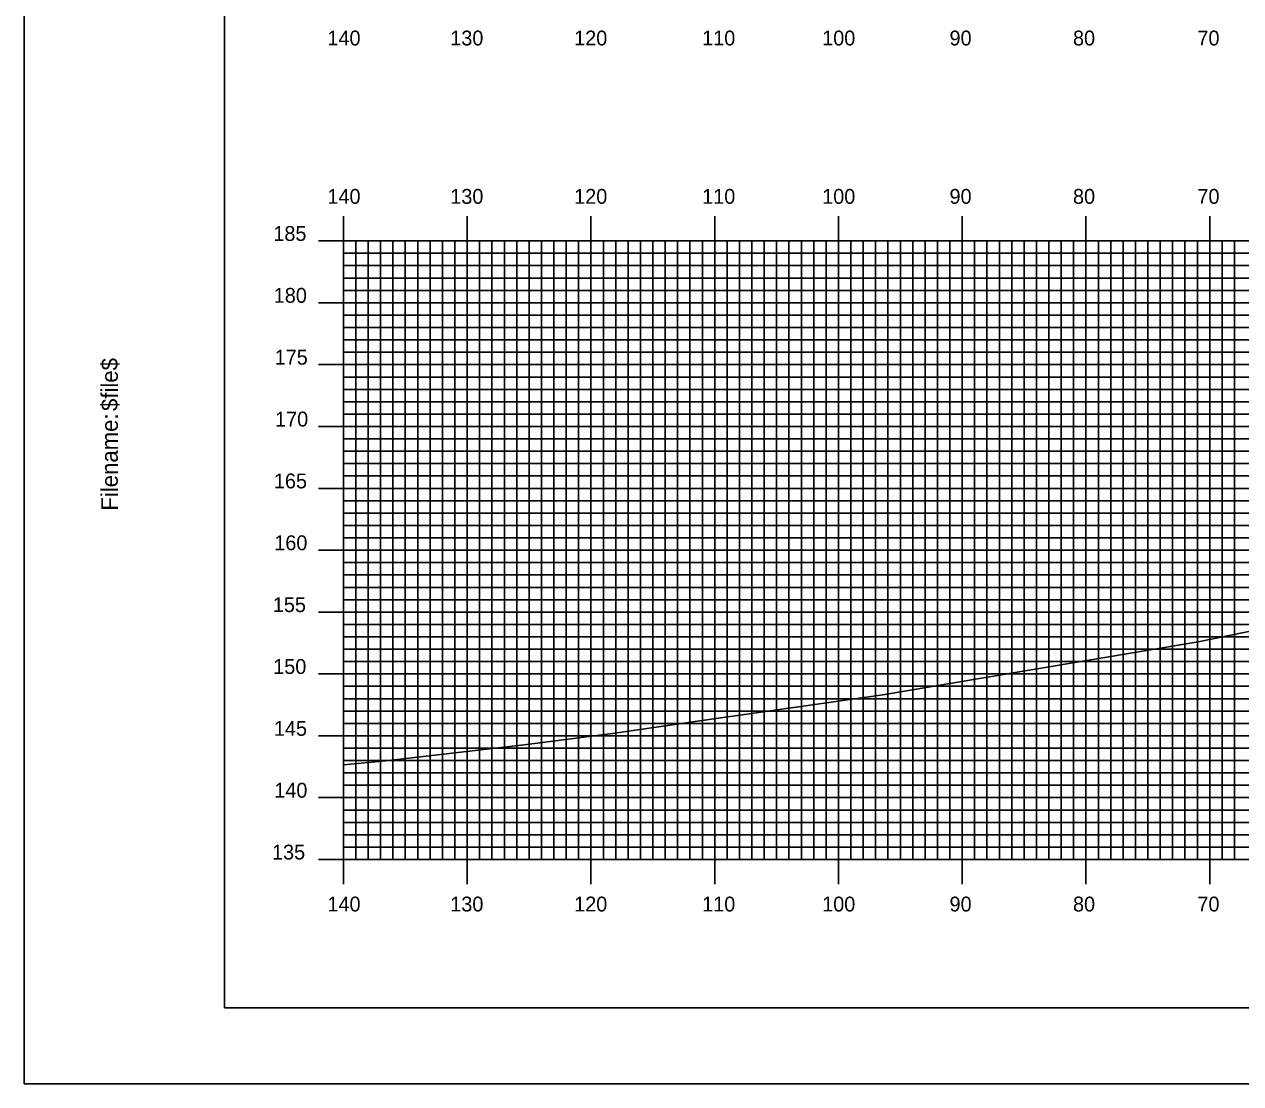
# Model space of a CAD drawing. Extents: x 1793666 to 1794009, y 442591 to 442811.
# Drawn here: x 1793665.5 to 1793763.8, y 442590.5 to 442676.2 of the extents above; entities that cross this region are included whole.
import ezdxf

# ---------------------------------------------------------------- set-up
doc = ezdxf.new("R2010")
doc.units = 0
for name, color, linetype in [('BORDER', 7, 'Continuous'), ('H_V ANNOTATION', 7, 'Continuous'), ('MAJOR', 7, 'Continuous'), ('MINOR', 7, 'Continuous'), ('PLOT BOUNDARY', 7, 'Continuous'), ('S_Roadway_Centerline', 7, 'Continuous')]:
    doc.layers.add(name, color=color, linetype=linetype)

msp = doc.modelspace()

# ---------------------------------------------------------------- linework, layer by layer
at = {"layer": 'BORDER'}
msp.add_lwpolyline([(1793681.714, 442596.665), (1794001.714, 442596.665), (1794001.714, 442806.665), (1793681.714, 442806.665)], close=True, dxfattribs=at)
at = {"layer": 'MAJOR'}
for p, q in [((1793691.314, 442660.669), (1793691.314, 442658.665)), ((1793701.314, 442660.669), (1793701.314, 442658.665)), ((1793711.314, 442660.669), (1793711.314, 442658.665)), ((1793721.314, 442660.669), (1793721.314, 442658.665)), ((1793731.314, 442660.669), (1793731.314, 442658.665)), ((1793741.314, 442660.669), (1793741.314, 442658.665)), ((1793751.314, 442660.669), (1793751.314, 442658.665)), ((1793761.314, 442660.669), (1793761.314, 442658.665)), ((1793689.31, 442658.665), (1793691.314, 442658.665)), ((1793691.314, 442658.665), (1793971.314, 442658.665)), ((1793691.314, 442608.665), (1793691.314, 442658.665)), ((1793691.314, 442608.665), (1793691.314, 442658.665)), ((1793691.314, 442658.665), (1793971.314, 442658.665)), ((1793701.314, 442608.665), (1793701.314, 442658.665)), ((1793711.314, 442608.665), (1793711.314, 442658.665)), ((1793721.314, 442608.665), (1793721.314, 442658.665)), ((1793731.314, 442608.665), (1793731.314, 442658.665)), ((1793741.314, 442608.665), (1793741.314, 442658.665)), ((1793751.314, 442608.665), (1793751.314, 442658.665)), ((1793761.314, 442608.665), (1793761.314, 442658.665)), ((1793689.31, 442653.665), (1793691.314, 442653.665)), ((1793691.314, 442653.665), (1793971.314, 442653.665)), ((1793689.31, 442648.665), (1793691.314, 442648.665)), ((1793691.314, 442648.665), (1793971.314, 442648.665)), ((1793689.31, 442643.665), (1793691.314, 442643.665)), ((1793691.314, 442643.665), (1793971.314, 442643.665)), ((1793689.31, 442638.665), (1793691.314, 442638.665)), ((1793691.314, 442638.665), (1793971.314, 442638.665)), ((1793689.31, 442633.665), (1793691.314, 442633.665)), ((1793691.314, 442633.665), (1793971.314, 442633.665)), ((1793689.31, 442628.665), (1793691.314, 442628.665)), ((1793691.314, 442628.665), (1793971.314, 442628.665)), ((1793689.31, 442623.665), (1793691.314, 442623.665)), ((1793691.314, 442623.665), (1793971.314, 442623.665)), ((1793689.31, 442618.665), (1793691.314, 442618.665)), ((1793691.314, 442618.665), (1793971.314, 442618.665)), ((1793689.31, 442613.665), (1793691.314, 442613.665)), ((1793691.314, 442613.665), (1793971.314, 442613.665)), ((1793689.31, 442608.665), (1793691.314, 442608.665)), ((1793691.314, 442608.665), (1793971.314, 442608.665)), ((1793691.314, 442608.665), (1793971.314, 442608.665)), ((1793691.314, 442606.661), (1793691.314, 442608.665)), ((1793701.314, 442606.661), (1793701.314, 442608.665)), ((1793711.314, 442606.661), (1793711.314, 442608.665)), ((1793721.314, 442606.661), (1793721.314, 442608.665)), ((1793731.314, 442606.661), (1793731.314, 442608.665)), ((1793741.314, 442606.661), (1793741.314, 442608.665)), ((1793751.314, 442606.661), (1793751.314, 442608.665)), ((1793761.314, 442606.661), (1793761.314, 442608.665))]:
    msp.add_line(p, q, dxfattribs=at)
at = {"layer": 'MINOR'}
for p, q in [((1793692.314, 442608.665), (1793692.314, 442658.665)), ((1793693.314, 442608.665), (1793693.314, 442658.665)), ((1793694.314, 442608.665), (1793694.314, 442658.665)), ((1793695.314, 442608.665), (1793695.314, 442658.665)), ((1793696.314, 442608.665), (1793696.314, 442658.665)), ((1793697.314, 442608.665), (1793697.314, 442658.665)), ((1793698.314, 442608.665), (1793698.314, 442658.665)), ((1793699.314, 442608.665), (1793699.314, 442658.665)), ((1793700.314, 442608.665), (1793700.314, 442658.665)), ((1793702.314, 442608.665), (1793702.314, 442658.665)), ((1793703.314, 442608.665), (1793703.314, 442658.665)), ((1793704.314, 442608.665), (1793704.314, 442658.665)), ((1793705.314, 442608.665), (1793705.314, 442658.665)), ((1793706.314, 442608.665), (1793706.314, 442658.665)), ((1793707.314, 442608.665), (1793707.314, 442658.665)), ((1793708.314, 442608.665), (1793708.314, 442658.665)), ((1793709.314, 442608.665), (1793709.314, 442658.665)), ((1793710.314, 442608.665), (1793710.314, 442658.665)), ((1793712.314, 442608.665), (1793712.314, 442658.665)), ((1793713.314, 442608.665), (1793713.314, 442658.665)), ((1793714.314, 442608.665), (1793714.314, 442658.665)), ((1793715.314, 442608.665), (1793715.314, 442658.665)), ((1793716.314, 442608.665), (1793716.314, 442658.665)), ((1793717.314, 442608.665), (1793717.314, 442658.665)), ((1793718.314, 442608.665), (1793718.314, 442658.665)), ((1793719.314, 442608.665), (1793719.314, 442658.665)), ((1793720.314, 442608.665), (1793720.314, 442658.665)), ((1793722.314, 442608.665), (1793722.314, 442658.665)), ((1793723.314, 442608.665), (1793723.314, 442658.665)), ((1793724.314, 442608.665), (1793724.314, 442658.665)), ((1793725.314, 442608.665), (1793725.314, 442658.665)), ((1793726.314, 442608.665), (1793726.314, 442658.665)), ((1793727.314, 442608.665), (1793727.314, 442658.665)), ((1793728.314, 442608.665), (1793728.314, 442658.665)), ((1793729.314, 442608.665), (1793729.314, 442658.665)), ((1793730.314, 442608.665), (1793730.314, 442658.665)), ((1793732.314, 442608.665), (1793732.314, 442658.665)), ((1793733.314, 442608.665), (1793733.314, 442658.665)), ((1793734.314, 442608.665), (1793734.314, 442658.665)), ((1793735.314, 442608.665), (1793735.314, 442658.665)), ((1793736.314, 442608.665), (1793736.314, 442658.665)), ((1793737.314, 442608.665), (1793737.314, 442658.665)), ((1793738.314, 442608.665), (1793738.314, 442658.665)), ((1793739.314, 442608.665), (1793739.314, 442658.665)), ((1793740.314, 442608.665), (1793740.314, 442658.665)), ((1793742.314, 442608.665), (1793742.314, 442658.665)), ((1793743.314, 442608.665), (1793743.314, 442658.665)), ((1793744.314, 442608.665), (1793744.314, 442658.665)), ((1793745.314, 442608.665), (1793745.314, 442658.665)), ((1793746.314, 442608.665), (1793746.314, 442658.665)), ((1793747.314, 442608.665), (1793747.314, 442658.665)), ((1793748.314, 442608.665), (1793748.314, 442658.665)), ((1793749.314, 442608.665), (1793749.314, 442658.665)), ((1793750.314, 442608.665), (1793750.314, 442658.665)), ((1793752.314, 442608.665), (1793752.314, 442658.665)), ((1793753.314, 442608.665), (1793753.314, 442658.665)), ((1793754.314, 442608.665), (1793754.314, 442658.665)), ((1793755.314, 442608.665), (1793755.314, 442658.665)), ((1793756.314, 442608.665), (1793756.314, 442658.665)), ((1793757.314, 442608.665), (1793757.314, 442658.665)), ((1793758.314, 442608.665), (1793758.314, 442658.665)), ((1793759.314, 442608.665), (1793759.314, 442658.665)), ((1793760.314, 442608.665), (1793760.314, 442658.665)), ((1793762.314, 442608.665), (1793762.314, 442658.665)), ((1793763.314, 442608.665), (1793763.314, 442658.665)), ((1793691.314, 442657.665), (1793971.314, 442657.665)), ((1793691.314, 442657.665), (1793693.318, 442657.665)), ((1793691.314, 442656.665), (1793971.314, 442656.665)), ((1793691.314, 442656.665), (1793693.318, 442656.665)), ((1793691.314, 442655.665), (1793971.314, 442655.665)), ((1793691.314, 442655.665), (1793693.318, 442655.665)), ((1793691.314, 442654.665), (1793971.314, 442654.665)), ((1793691.314, 442654.665), (1793693.318, 442654.665)), ((1793691.314, 442652.665), (1793971.314, 442652.665)), ((1793691.314, 442652.665), (1793693.318, 442652.665)), ((1793691.314, 442651.665), (1793971.314, 442651.665)), ((1793691.314, 442651.665), (1793693.318, 442651.665)), ((1793691.314, 442650.665), (1793971.314, 442650.665)), ((1793691.314, 442650.665), (1793693.318, 442650.665)), ((1793691.314, 442649.665), (1793971.314, 442649.665)), ((1793691.314, 442649.665), (1793693.318, 442649.665)), ((1793691.314, 442647.665), (1793971.314, 442647.665)), ((1793691.314, 442647.665), (1793693.318, 442647.665)), ((1793691.314, 442646.665), (1793971.314, 442646.665)), ((1793691.314, 442646.665), (1793693.318, 442646.665)), ((1793691.314, 442645.665), (1793971.314, 442645.665)), ((1793691.314, 442645.665), (1793693.318, 442645.665)), ((1793691.314, 442644.665), (1793971.314, 442644.665)), ((1793691.314, 442644.665), (1793693.318, 442644.665)), ((1793691.314, 442642.665), (1793971.314, 442642.665)), ((1793691.314, 442642.665), (1793693.318, 442642.665)), ((1793691.314, 442641.665), (1793971.314, 442641.665)), ((1793691.314, 442641.665), (1793693.318, 442641.665)), ((1793691.314, 442640.665), (1793971.314, 442640.665)), ((1793691.314, 442640.665), (1793693.318, 442640.665)), ((1793691.314, 442639.665), (1793971.314, 442639.665)), ((1793691.314, 442639.665), (1793693.318, 442639.665)), ((1793691.314, 442637.665), (1793971.314, 442637.665)), ((1793691.314, 442637.665), (1793693.318, 442637.665)), ((1793691.314, 442636.665), (1793971.314, 442636.665)), ((1793691.314, 442636.665), (1793693.318, 442636.665)), ((1793691.314, 442635.665), (1793971.314, 442635.665)), ((1793691.314, 442635.665), (1793693.318, 442635.665)), ((1793691.314, 442634.665), (1793971.314, 442634.665)), ((1793691.314, 442634.665), (1793693.318, 442634.665)), ((1793691.314, 442632.665), (1793971.314, 442632.665)), ((1793691.314, 442632.665), (1793693.318, 442632.665)), ((1793691.314, 442631.665), (1793971.314, 442631.665)), ((1793691.314, 442631.665), (1793693.318, 442631.665)), ((1793691.314, 442630.665), (1793971.314, 442630.665)), ((1793691.314, 442630.665), (1793693.318, 442630.665)), ((1793691.314, 442629.665), (1793971.314, 442629.665)), ((1793691.314, 442629.665), (1793693.318, 442629.665)), ((1793691.314, 442627.665), (1793971.314, 442627.665)), ((1793691.314, 442627.665), (1793693.318, 442627.665)), ((1793691.314, 442626.665), (1793971.314, 442626.665)), ((1793691.314, 442626.665), (1793693.318, 442626.665)), ((1793691.314, 442625.665), (1793971.314, 442625.665)), ((1793691.314, 442625.665), (1793693.318, 442625.665)), ((1793691.314, 442624.665), (1793971.314, 442624.665)), ((1793691.314, 442624.665), (1793693.318, 442624.665)), ((1793691.314, 442622.665), (1793971.314, 442622.665)), ((1793691.314, 442622.665), (1793693.318, 442622.665)), ((1793691.314, 442621.665), (1793971.314, 442621.665)), ((1793691.314, 442621.665), (1793693.318, 442621.665)), ((1793691.314, 442620.665), (1793971.314, 442620.665)), ((1793691.314, 442620.665), (1793693.318, 442620.665)), ((1793691.314, 442619.665), (1793971.314, 442619.665)), ((1793691.314, 442619.665), (1793693.318, 442619.665)), ((1793691.314, 442617.665), (1793971.314, 442617.665)), ((1793691.314, 442617.665), (1793693.318, 442617.665)), ((1793691.314, 442616.665), (1793971.314, 442616.665)), ((1793691.314, 442616.665), (1793693.318, 442616.665)), ((1793691.314, 442615.665), (1793971.314, 442615.665)), ((1793691.314, 442615.665), (1793693.318, 442615.665)), ((1793691.314, 442614.665), (1793971.314, 442614.665)), ((1793691.314, 442614.665), (1793693.318, 442614.665)), ((1793691.314, 442612.665), (1793971.314, 442612.665)), ((1793691.314, 442612.665), (1793693.318, 442612.665)), ((1793691.314, 442611.665), (1793971.314, 442611.665)), ((1793691.314, 442611.665), (1793693.318, 442611.665)), ((1793691.314, 442610.665), (1793971.314, 442610.665)), ((1793691.314, 442610.665), (1793693.318, 442610.665)), ((1793691.314, 442609.665), (1793971.314, 442609.665)), ((1793691.314, 442609.665), (1793693.318, 442609.665))]:
    msp.add_line(p, q, dxfattribs=at)
at = {"layer": 'PLOT BOUNDARY'}
msp.add_lwpolyline([(1793665.527, 442590.547), (1794005.527, 442590.547), (1794005.527, 442810.547), (1793665.527, 442810.547)], close=True, dxfattribs=at)
at = {"layer": 'S_Roadway_Centerline'}
msp.add_lwpolyline([(1793691.314, 442616.321), (1793694.735, 442616.634), (1793705.906, 442617.941), (1793713.058, 442618.85), (1793720.307, 442619.904), (1793734.893, 442621.964), (1793742.87, 442623.311), (1793760.386, 442626.267), (1793767.9, 442627.802), (1793778.333, 442629.328), (1793783.719, 442630.008), (1793786.541, 442630.469), (1793796.306, 442631.583), (1793805.069, 442632.722), (1793812.568, 442633.664), (1793830.499, 442635.729), (1793833.572, 442636.072), (1793854.537, 442638.443), (1793858.019, 442638.691), (1793859.506, 442639.026), (1793861.747, 442639.479), (1793863.669, 442639.425)], dxfattribs=at)

# ---------------------------------------------------------------- texts
at = {"layer": 'BORDER'}
for s, p in [('$file$', (1793673.083, 442644.916)), ('Filename:', (1793673.083, 442636.862))]:
    msp.add_text(s, height=1.3392, rotation=90, dxfattribs=at).set_placement(p)
at = {"layer": 'H_V ANNOTATION'}
for s, p in [('140', (1793690.018, 442674.465)), ('130', (1793699.944, 442674.465)), ('120', (1793709.954, 442674.465)), ('110', (1793720.297, 442674.465)), ('100', (1793729.997, 442674.465)), ('90', (1793740.286, 442674.465)), ('80', (1793750.264, 442674.465)), ('70', (1793760.318, 442674.465)), ('140', (1793690.018, 442661.665)), ('130', (1793699.944, 442661.665)), ('120', (1793709.954, 442661.665)), ('110', (1793720.297, 442661.665)), ('100', (1793729.997, 442661.665)), ('90', (1793740.286, 442661.665)), ('80', (1793750.264, 442661.665)), ('70', (1793760.318, 442661.665)), ('185', (1793685.648, 442658.665)), ('180', (1793685.68, 442653.665)), ('175', (1793685.755, 442648.665)), ('170', (1793685.787, 442643.665)), ('165', (1793685.691, 442638.665)), ('160', (1793685.723, 442633.665)), ('155', (1793685.605, 442628.665)), ('150', (1793685.637, 442623.665)), ('145', (1793685.691, 442618.665)), ('140', (1793685.723, 442613.665)), ('135', (1793685.541, 442608.665)), ('140', (1793690.018, 442604.465)), ('130', (1793699.944, 442604.465)), ('120', (1793709.954, 442604.465)), ('110', (1793720.297, 442604.465)), ('100', (1793729.997, 442604.465)), ('90', (1793740.286, 442604.465)), ('80', (1793750.264, 442604.465)), ('70', (1793760.318, 442604.465))]:
    msp.add_text(s, height=1.2, dxfattribs=at).set_placement(p)
at = {"layer": 'MAJOR'}
msp.add_text('-', height=0.012, dxfattribs=at).set_placement((1793691.305, 442608.665))

doc.saveas('drawing.dxf')
